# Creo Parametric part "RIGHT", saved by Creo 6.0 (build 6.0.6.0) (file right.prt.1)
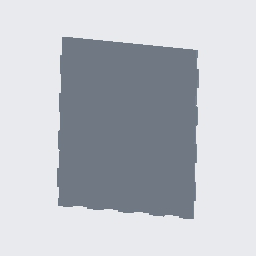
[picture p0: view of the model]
Units: Inch lbm Second (Pro/E Default); INCH, POUND, SECS

Created from: INLBS_PART_SOLID.PRT

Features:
  1. datum plane "RIGHT"
  2. datum plane "TOP"
  3. datum plane "FRONT"
  4. coordinate system
  5. sketch "Sketch 1"
  6. extrusion "Extrude 1"

Surfaces: 54 plane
